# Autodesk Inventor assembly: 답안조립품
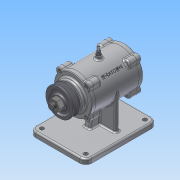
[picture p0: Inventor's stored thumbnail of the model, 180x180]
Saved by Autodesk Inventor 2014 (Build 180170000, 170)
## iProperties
Created: 2016-01
Part Number: 답안조립품
Document SubType Name: Assembly
Designer: Administrator
Author: Administrator
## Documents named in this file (12)
- C:\Users\Administrator\Desktop\460108V1005\답안조립품.iam
- C:\Users\Administrator\Desktop\460108V1005\1-본체.ipt
- C:\Users\Administrator\Desktop\460108V1005\V-벨트풀리.ipt
- C:\Users\Administrator\Desktop\460108V1005\너트 M12x1.25.ipt
- C:\Users\Administrator\Desktop\460108V1005\니플 M 6 x 0.75.ipt
- C:\Users\Administrator\Desktop\460108V1005\베어링 6204.ipt
- C:\Users\Administrator\Desktop\460108V1005\볼트 M4 x 12.ipt
- C:\Users\Administrator\Desktop\460108V1005\오일실.ipt
- C:\Users\Administrator\Desktop\460108V1005\축.ipt
- C:\Users\Administrator\Desktop\460108V1005\커버.ipt
- C:\Users\Administrator\Desktop\460108V1005\커버2.ipt
- C:\Users\Administrator\Desktop\460108V1005\키(4 x 4 x 12).ipt
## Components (7 placed, 6 different names)
1. 1-본체:1
2. V-벨트풀리:1 — 각도:2
3. KS B 1012 클래스 1 일반 - 미터 M12x1.25:1
4. KS B 2023 6204 - 20 x 47 x 14:1
5. KS B 2804 D D - 20 32 8:1
6. KS B 1311 (I) 4 x 4 x 12:1 — 각도:1, 각도:2
7. KS B 2023 6204 - 20 x 47 x 14:2
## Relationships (2: Angle 2)
- 각도:1 [Angle]: KS B 1311 (I) 4 x 4 x 12:1
- 각도:2 [Angle]: V-벨트풀리:1 ↔ KS B 1311 (I) 4 x 4 x 12:1
